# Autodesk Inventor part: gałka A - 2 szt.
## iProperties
Created: 2024-06
Part Number: gałka A - 2 szt.
Document SubType Name: Modeling
Designer: Tomasz Łysek
Density: 1 g/cm^3
Author: Tomasz Łysek
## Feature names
1. Wyciągnięcie proste1 [Extrusion]
2. Wyciągnięcie proste2 [Extrusion]
3. Wyciągnięcie proste3 [Extrusion]
4. Wyciągnięcie proste4 [Extrusion]
